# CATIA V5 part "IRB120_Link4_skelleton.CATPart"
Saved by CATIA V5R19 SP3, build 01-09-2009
Part number: IRB120_Link4_skelleton
Bounding box of the stored display mesh (mm): x -172 to 0, y 0 to 50, z 0 to 0
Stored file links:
  Z:\Projects\ABB_Robotics\ABB LIB\V5\V5PARTS\ABB\120\IRB120_Link4_skelleton.CATPart
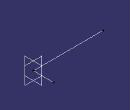
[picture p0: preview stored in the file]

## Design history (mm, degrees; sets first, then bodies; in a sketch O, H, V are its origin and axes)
Body1 (main body)
  Line1: type PtPt, FirstPoint {point type Coord, X 0, Y 0, Z 0}, SecondPoint {point type Coord, X -172, Y 0, Z 0, RefPoint {point type Coord, X 0, Y 0, Z 0}}
  Line2: type PtPt, FirstPoint vertex of Line1, SecondPoint {point type Coord, X 0, Y 50, Z 0, RefPoint vertex of Line1}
